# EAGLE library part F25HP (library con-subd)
SUB-D
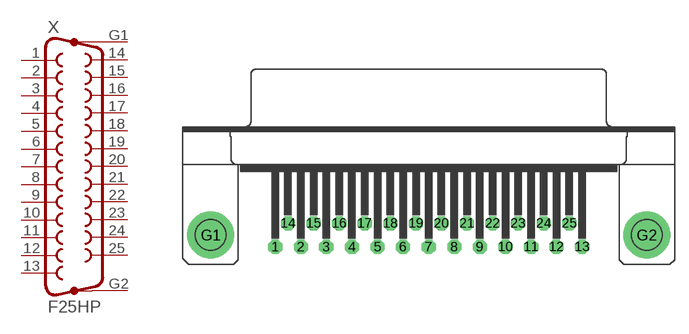
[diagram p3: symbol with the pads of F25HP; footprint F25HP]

Designator prefix X

## F25HP (OC_FARNELL: unknown; OC_NEWARK: unknown)  [F25HP]
1  1  pas
2  2  pas
3  3  pas
4  4  pas
5  5  pas
6  6  pas
7  7  pas
8  8  pas
9  9  pas
10  10  pas
11  11  pas
12  12  pas
13  13  pas
14  14  pas
15  15  pas
16  16  pas
17  17  pas
18  18  pas
19  19  pas
20  20  pas
21  21  pas
22  22  pas
23  23  pas
24  24  pas
25  25  pas
G1  G1  pas
G2  G2  pas

## Footprint F25HP (pad centres in mm)
SUB-D
drill 1.016 octagon: 1 -16.561,-1.27; 2 -13.792,-1.27; 3 -11.049,-1.27; 4 -8.28,-1.27; 5 -5.512,-1.27; 6 -2.769,-1.27; 7 0,-1.27; 8 2.769,-1.27; 9 5.512,-1.27; 10 8.28,-1.27; 11 11.049,-1.27; 12 13.792,-1.27; 13 16.561,-1.27; 14 -15.189,1.27; 15 -12.421,1.27; 16 -9.652,1.27; 17 -6.909,1.27; 18 -4.14,1.27; 19 -1.372,1.27; 20 1.372,1.27; 21 4.14,1.27; 22 6.909,1.27; 23 9.652,1.27; 24 12.421,1.27; 25 15.189,1.27
drill 3.302 pad 5.08 round: G1 -23.52,0; G2 23.52,0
